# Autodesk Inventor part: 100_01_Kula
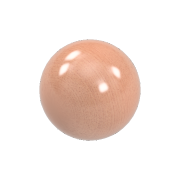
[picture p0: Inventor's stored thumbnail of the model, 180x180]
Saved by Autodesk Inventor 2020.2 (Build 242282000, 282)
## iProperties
Created: 2020-03
Part Number: 100_01_Kula
Material: Drewno (dąb)
Document SubType Name: Modeling
Designer: F.Stasiak
Density: 0.76 g/cm^3
Appearance: Dąb biały — naturalny — średni połysk
Catalog Web Link: www.expertbooks.pl
Manager: www.cadconsulting.pl
Company: Fabian Stasiak CAD Consulting
Author: F.Stasiak
Subject: Zbiór ćwiczeń. Autodesk Inventor 2020. Kurs Professional
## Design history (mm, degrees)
sketch "Szkic1"
  geometry: L1 (0, 175)-(0, -175); A1 r 175 centre (0, 0) between (0, -175) and (0, 175); 2 further points
  constraints: 2 coincident, 2 end point, 2 point on circle, 1 centre point, 1 midpoint, 1 vertical
  dimensions: "d0" = 350 distance of L1.start L1.end
revolve "Obrót1" sketch "Szkic1" stored, may be unused: angle "d1" = 90 deg
node "Bryła1"
